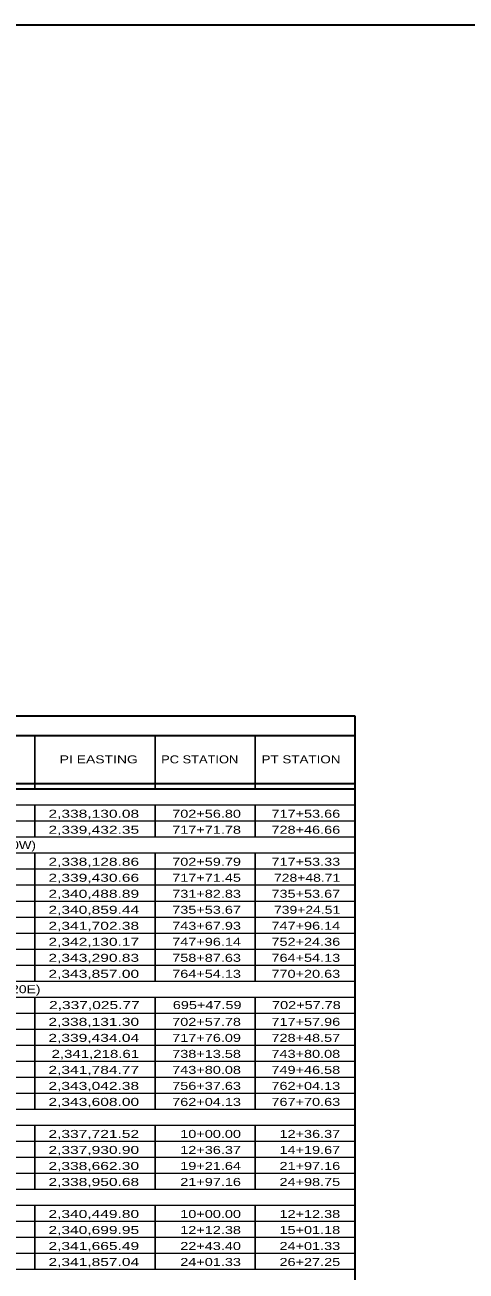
# Model space of a CAD drawing. Extents: x 1953053 to 1967065, y 7363860 to 7371201.
# Drawn here: x 1959156 to 1959817, y 7369333 to 7371201 of the extents above; entities that cross this region are included whole.
import ezdxf
from ezdxf.enums import TextEntityAlignment as Align

# ---------------------------------------------------------------- set-up
doc = ezdxf.new("R2010")
doc.units = 0
doc.header["$LTSCALE"] = 4.8
doc.layers.add('10', color=7, linetype='Continuous')
doc.layers.add('12', color=7, linetype='Continuous', lineweight=25)
doc.layers.add('62', color=7, linetype='Continuous', lineweight=35)

msp = doc.modelspace()

# ---------------------------------------------------------------- linework, layer by layer
at = {"layer": '12', "lineweight": 35}
for p, q in [((1959650.637, 7370164.879), (1957927.305, 7370164.879)), ((1959650.637, 7368423.747), (1959650.637, 7370164.879)), ((1957927.305, 7370136.079), (1959650.637, 7370136.079)), ((1957927.305, 7370064.079), (1959650.637, 7370064.079)), ((1957927.305, 7370055.746), (1959650.637, 7370055.746))]:
    msp.add_line(p, q, dxfattribs=at)
at = {"layer": '12'}
for p, q in [((1959170.637, 7370136.079), (1959170.637, 7370055.746)), ((1959350.637, 7370136.079), (1959350.637, 7370055.746)), ((1959500.637, 7370136.079), (1959500.637, 7370055.746)), ((1959170.637, 7370031.746), (1959170.637, 7369983.746)), ((1959350.637, 7370031.746), (1959350.637, 7369983.746)), ((1959500.637, 7370031.746), (1959500.637, 7369983.746)), ((1959170.637, 7369959.746), (1959170.637, 7369767.746)), ((1959350.637, 7369959.746), (1959350.637, 7369767.746)), ((1959500.637, 7369959.746), (1959500.637, 7369767.746)), ((1959170.637, 7369743.746), (1959170.637, 7369575.746)), ((1959350.637, 7369743.746), (1959350.637, 7369575.746)), ((1959500.637, 7369743.746), (1959500.637, 7369575.746)), ((1959170.637, 7369551.746), (1959170.637, 7369455.746)), ((1959350.637, 7369551.746), (1959350.637, 7369455.746)), ((1959500.637, 7369551.746), (1959500.637, 7369455.746)), ((1959170.637, 7369431.746), (1959170.637, 7369335.746)), ((1959350.637, 7369431.746), (1959350.637, 7369335.746)), ((1959500.637, 7369431.746), (1959500.637, 7369335.746))]:
    msp.add_line(p, q, dxfattribs=at)
at = {"layer": '12', "lineweight": 13}
for p, q in [((1957927.305, 7370007.746), (1959650.637, 7370007.746)), ((1957927.305, 7369983.746), (1959650.637, 7369983.746)), ((1957927.305, 7369959.746), (1959650.637, 7369959.746)), ((1957927.305, 7369935.746), (1959650.637, 7369935.746)), ((1957927.305, 7369911.746), (1959650.637, 7369911.746)), ((1957927.305, 7369887.746), (1959650.637, 7369887.746)), ((1957927.305, 7369863.746), (1959650.637, 7369863.746)), ((1957927.305, 7369839.746), (1959650.637, 7369839.746)), ((1957927.305, 7369815.746), (1959650.637, 7369815.746)), ((1957927.305, 7369791.746), (1959650.637, 7369791.746)), ((1957927.305, 7369767.746), (1959650.637, 7369767.746)), ((1957927.305, 7369743.746), (1959650.637, 7369743.746)), ((1957927.305, 7369719.746), (1959650.637, 7369719.746)), ((1957927.305, 7369695.746), (1959650.637, 7369695.746)), ((1957927.305, 7369671.746), (1959650.637, 7369671.746)), ((1957927.305, 7369647.746), (1959650.637, 7369647.746)), ((1957927.305, 7369623.746), (1959650.637, 7369623.746)), ((1957927.305, 7369599.746), (1959650.637, 7369599.746)), ((1957927.305, 7369551.746), (1959650.637, 7369551.746)), ((1957927.305, 7369527.746), (1959650.637, 7369527.746)), ((1957927.305, 7369503.746), (1959650.637, 7369503.746)), ((1957927.305, 7369479.746), (1959650.637, 7369479.746)), ((1957927.305, 7369455.746), (1959650.637, 7369455.746)), ((1957927.305, 7369431.746), (1959650.637, 7369431.746)), ((1957927.305, 7369407.746), (1959650.637, 7369407.746)), ((1957927.305, 7369383.746), (1959650.637, 7369383.746)), ((1957927.305, 7369359.746), (1959650.637, 7369359.746)), ((1957927.305, 7369335.746), (1959650.637, 7369335.746))]:
    msp.add_line(p, q, dxfattribs=at)
for points in [[(1957927.305, 7370031.746), (1958712.39, 7370031.746), (1959650.637, 7370031.746)], [(1957927.305, 7369575.746), (1959174.539, 7369575.746), (1959650.637, 7369575.746)]]:
    msp.add_lwpolyline(points, dxfattribs=at)
at = {"layer": '62'}
msp.add_lwpolyline([(1953052.784, 7371201.108), (1967065.314, 7371201.108), (1967065.314, 7363859.877), (1953052.784, 7363859.877)], close=True, dxfattribs=at)

# ---------------------------------------------------------------- texts
at = {"layer": '10'}
for s, width, p in [('2,338,130.08', 1.45, (1959326.839, 7370012.573)), ('702+56.80', 1.35, (1959479.417, 7370012.573)), ('717+53.66', 1.35, (1959628.149, 7370012.573)), ('2,339,432.35', 1.45, (1959326.839, 7369988.573)), ('717+71.78', 1.35, (1959479.417, 7369988.573)), ('728+46.66', 1.35, (1959628.149, 7369988.573)), ('2,338,128.86', 1.45, (1959326.839, 7369940.573)), ('702+59.79', 1.35, (1959479.417, 7369940.573)), ('717+53.33', 1.35, (1959628.149, 7369940.573)), ('2,339,430.66', 1.45, (1959326.839, 7369916.573)), ('717+71.45', 1.35, (1959479.417, 7369916.573)), ('728+48.71', 1.3, (1959628.149, 7369916.573)), ('2,340,488.89', 1.45, (1959326.839, 7369892.573)), ('731+82.83', 1.35, (1959479.417, 7369892.573)), ('735+53.67', 1.35, (1959628.149, 7369892.573)), ('2,340,859.44', 1.45, (1959326.839, 7369868.573)), ('735+53.67', 1.35, (1959479.417, 7369868.573)), ('739+24.51', 1.3, (1959628.149, 7369868.573)), ('2,341,702.38', 1.45, (1959326.839, 7369844.573)), ('743+67.93', 1.35, (1959479.417, 7369844.573)), ('747+96.14', 1.35, (1959628.149, 7369844.573)), ('2,342,130.17', 1.45, (1959326.839, 7369820.573)), ('747+96.14', 1.35, (1959479.417, 7369820.573)), ('752+24.36', 1.35, (1959628.149, 7369820.573)), ('2,343,290.83', 1.45, (1959326.839, 7369796.573)), ('758+87.63', 1.35, (1959479.417, 7369796.573)), ('764+54.13', 1.35, (1959628.149, 7369796.573)), ('2,343,857.00', 1.45, (1959326.839, 7369772.573)), ('764+54.13', 1.35, (1959479.417, 7369772.573)), ('770+20.63', 1.35, (1959628.149, 7369772.573)), ('2,337,025.77', 1.45, (1959327.713, 7369725.764)), ('695+47.59', 1.35, (1959480.291, 7369725.764)), ('702+57.78', 1.35, (1959629.023, 7369725.764)), ('2,338,131.30', 1.45, (1959326.839, 7369700.573)), ('702+57.78', 1.35, (1959479.417, 7369700.573)), ('717+57.96', 1.35, (1959628.149, 7369700.573)), ('2,339,434.04', 1.45, (1959326.839, 7369676.573)), ('717+76.09', 1.35, (1959479.417, 7369676.573)), ('728+48.57', 1.35, (1959628.149, 7369676.573)), ('2,341,218.61', 1.4, (1959326.839, 7369652.573)), ('738+13.58', 1.35, (1959479.417, 7369652.573)), ('743+80.08', 1.35, (1959628.149, 7369652.573)), ('2,341,784.77', 1.45, (1959326.839, 7369628.573)), ('743+80.08', 1.35, (1959479.417, 7369628.573)), ('749+46.58', 1.35, (1959628.149, 7369628.573)), ('2,343,042.38', 1.45, (1959326.839, 7369604.573)), ('756+37.63', 1.35, (1959479.417, 7369604.573)), ('762+04.13', 1.35, (1959628.149, 7369604.573)), ('2,343,608.00', 1.45, (1959326.839, 7369580.573)), ('762+04.13', 1.35, (1959479.417, 7369580.573)), ('767+70.63', 1.35, (1959628.149, 7369580.573)), ('2,337,721.52', 1.45, (1959326.839, 7369532.573)), ('10+00.00', 1.35, (1959479.417, 7369532.573)), ('12+36.37', 1.35, (1959628.149, 7369532.573)), ('2,337,930.90', 1.45, (1959326.839, 7369508.573)), ('12+36.37', 1.35, (1959479.417, 7369508.573)), ('14+19.67', 1.35, (1959628.149, 7369508.573)), ('2,338,662.30', 1.45, (1959326.839, 7369484.573)), ('19+21.64', 1.35, (1959479.417, 7369484.573)), ('21+97.16', 1.35, (1959628.149, 7369484.573)), ('2,338,950.68', 1.45, (1959326.839, 7369460.573)), ('21+97.16', 1.35, (1959479.417, 7369460.573)), ('24+98.75', 1.35, (1959628.149, 7369460.573)), ('2,340,449.80', 1.45, (1959326.839, 7369412.573)), ('10+00.00', 1.35, (1959479.417, 7369412.573)), ('12+12.38', 1.35, (1959628.149, 7369412.573)), ('2,340,699.95', 1.45, (1959326.839, 7369388.573)), ('12+12.38', 1.35, (1959479.417, 7369388.573)), ('15+01.18', 1.35, (1959628.149, 7369388.573)), ('2,341,665.49', 1.45, (1959326.839, 7369364.573)), ('22+43.40', 1.35, (1959479.417, 7369364.573)), ('24+01.33', 1.35, (1959628.149, 7369364.573)), ('2,341,857.04', 1.45, (1959326.839, 7369340.573)), ('24+01.33', 1.35, (1959479.417, 7369340.573)), ('26+27.25', 1.35, (1959628.149, 7369340.573))]:
    msp.add_text(s, height=12, dxfattribs=dict(at, width=width)).set_placement(p, align=Align.RIGHT)
for s, width, p in [('IH 820 WB GENERAL PURPOSE MAIN LANES BASELINE (GP820W)', 1.25, (1958855.637, 7369965.54)), ('IH 820 EB GENERAL PURPOSE MAIN LANES BASELINE (GP820E)', 1.3, (1958855.637, 7369749.54))]:
    msp.add_text(s, height=12, dxfattribs=dict(at, width=width)).set_placement(p, align=Align.CENTER)
at = {"layer": '12'}
for s, width, p in [('PI EASTING', 1.3, (1959266.341, 7370094.078)), ('PC STATION', 1.2, (1959417.646, 7370094.078)), ('PT STATION', 1.25, (1959569.417, 7370094.078))]:
    msp.add_text(s, height=12, dxfattribs=dict(at, width=width)).set_placement(p, align=Align.CENTER)

doc.saveas('drawing.dxf')
